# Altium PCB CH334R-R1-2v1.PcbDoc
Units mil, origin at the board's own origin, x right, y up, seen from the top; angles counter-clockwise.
Board outline 3110.24 x 866.14 mil, 2 copper layers (Top Layer, Bottom Layer); 16 components, 18 nets, 84 pads, 280 vias.
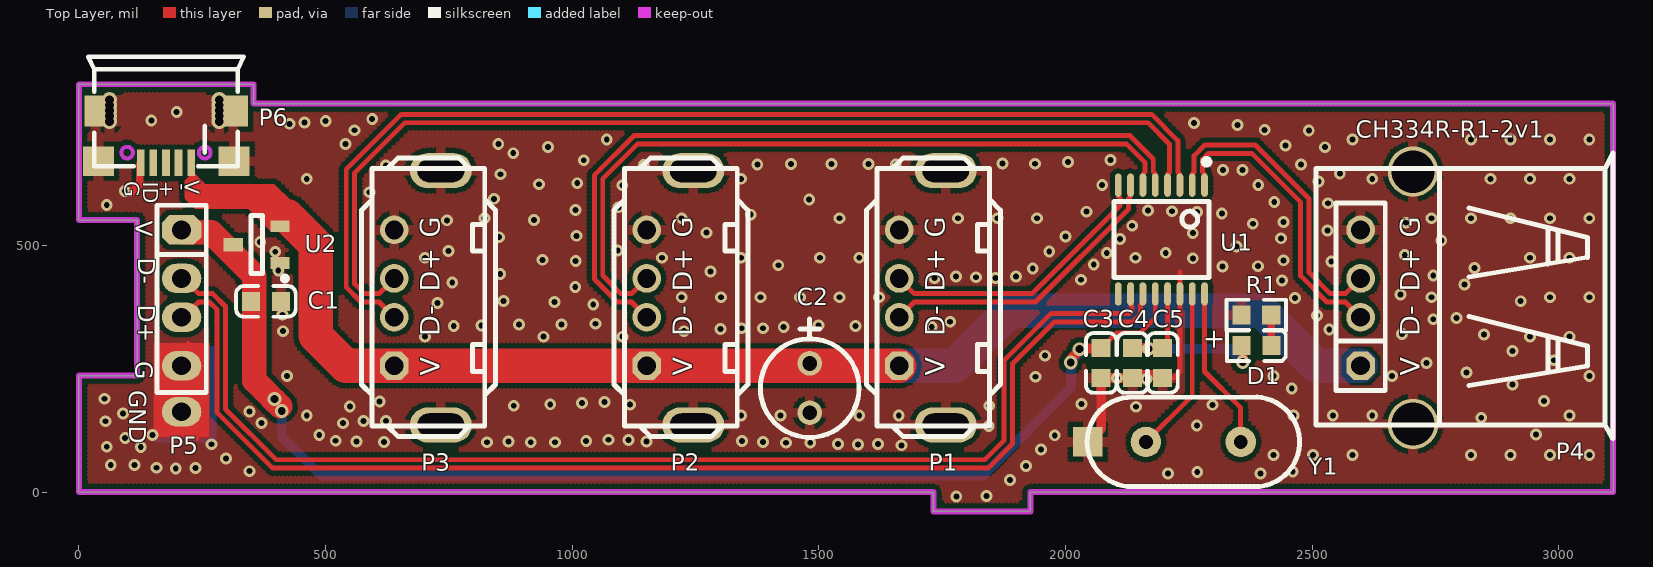
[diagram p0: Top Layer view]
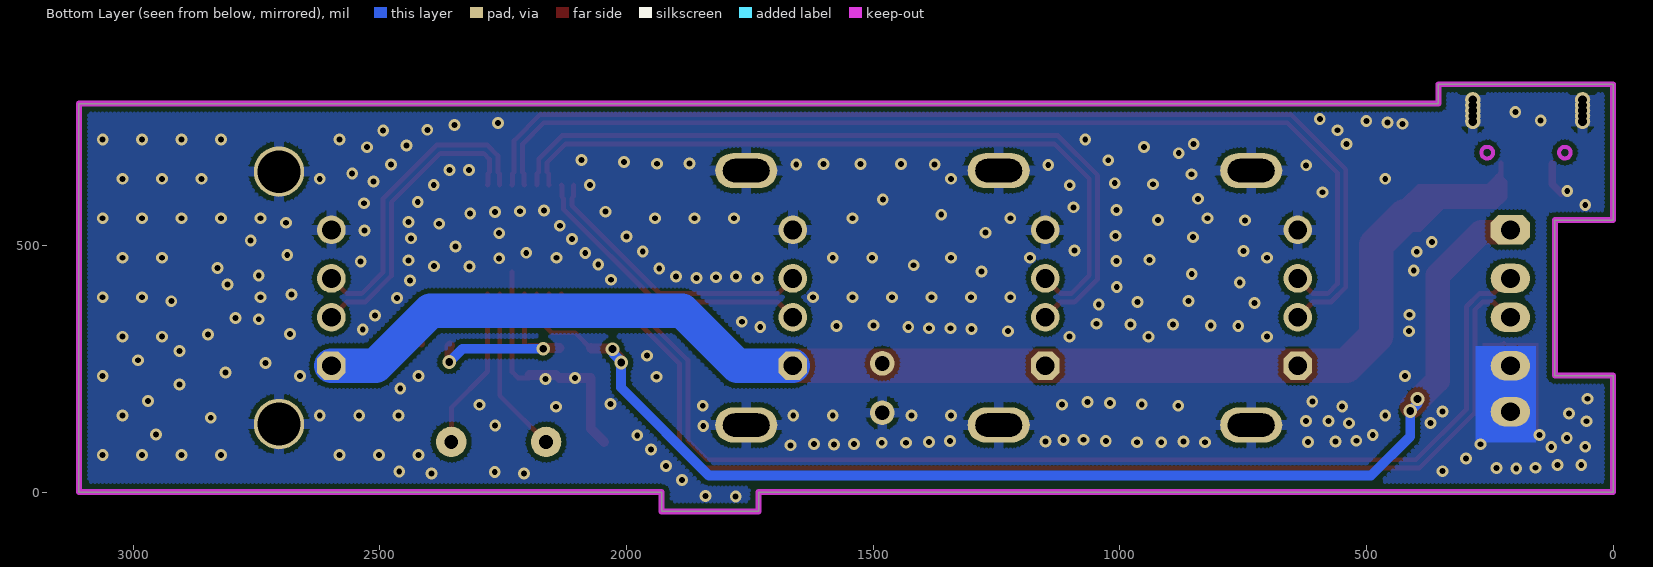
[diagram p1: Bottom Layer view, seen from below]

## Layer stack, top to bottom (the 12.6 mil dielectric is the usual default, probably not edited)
Top Solder: solder mask 0.4, Solder Resist, Dk 3.5
Top Layer: signal copper 1.4
Dielectric 1: dielectric 12.6, FR-4, Dk 4.8
Bottom Layer: signal copper 1.4
Bottom Solder: solder mask 0.4, Solder Resist, Dk 3.5

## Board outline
0,0 0,236.22 118.11,236.22 118.11,551.18 0,551.18 0,826.77 354.33,826.77 354.33,787.4 3110.24,787.4 3110.24,0 1929.13,0 1929.13,-39.37 1732.28,-39.37 1732.28,0

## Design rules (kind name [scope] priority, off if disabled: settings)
Clearance Clearance_1 [InPolygon] p1: gap=10 ignorepadtopadclearanceinfootprint=FALSE
Clearance [All] p2: gap=6 ignorepadtopadclearanceinfootprint=FALSE except(8: Arc-Via Track-Via SMDPad-Via THPad-Via Via-Via Via-Fill Via-Poly Via-Region Via-Hole)
ComponentClearance [All] p1 off: gap=10 collisioncheckmode=3 verticalgap=10 showdistances=FALSE
DiffPairsRouting [All] p1: maxlimit=10 minlimit=7 mostfreqgap=8 toplayer_minwidth=6 toplayer_maxwidth=15 toplayer_prefwidth=8 bottomlayer_minwidth=6 bottomlayer_maxwidth=15 bottomlayer_prefwidth=8 maxuncoupledlength=500
MinimumSolderMaskSliver [All] p1 off: minsoldermaskwidth=10
PolygonConnect PolygonConnect_1 [IsVia] p1: connectstyle=Direct reliefconductorwidth=10 reliefentries=4 polygonreliefangle="90 Angle" airgapwidth=10
PolygonConnect [All] p2: connectstyle=Relief reliefconductorwidth=20 reliefentries=4 polygonreliefangle="90 Angle" airgapwidth=10
RoutingVias [All] p1: holewidth=16 width=28 viastyle="Through Hole" minholewidth=12 minwidth=24 maxholewidth=28 maxwidth=50
SilkToSilkClearance [All] p1 off: silktosilkclearance=10
SilkToSolderMaskClearance [IsPad] p1 off: minsilkscreentomaskgap=10 clearancetoexposedcopper=TRUE
SolderMaskExpansion [All] p1: expansion=4 istentingtop=FALSE
Width [All] p1: maxlimit=100 minlimit=6 preferedwidth=10
25 further rules are at their usual default settings.

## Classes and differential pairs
component class CH334R-R1-2v1: C1 C2 D1 P1 P2 P3 P4 P5 P6 R1 U1 U2 Y1
differential pair UD: +UD_p -UD_n
differential pair UD4: +UD4_p -UD4_n
differential pair UD3: +UD3_p -UD3_n
differential pair UD2: +UD2_p -UD2_n
differential pair UD1: +UD1_p -UD1_n

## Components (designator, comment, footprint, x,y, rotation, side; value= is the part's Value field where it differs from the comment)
C1 "10uF" 0603_C 348.8,386.46 r0 top
C2 "220uF" CD0.1 1481.53,260.82 r270 top
C3 "1uF" 0603_C 2072.52,291.96 r270 top
C4 "0.1uF" 0603_C 2136.15,291.96 r270 top
C5 "10uF" 0603_C 2196.61,291.96 r270 top
D1 "LED" 0603+ 2357.27,297.04 r0 top
P1 "USB" USB2.0-A-F-TH_4P-V_13.7mm 1662.83,255.91 r180 top
P2 "USB" USB2.0-A-F-TH_4P-V_13.7mm 1151.02,255.91 r180 top
P3 "USB" USB2.0-A-F-TH_4P-V_13.7mm 639.21,255.91 r180 top
P4 "USB" USBAF#1 2598.25,255.91 r90 top
P5 "USB" USBAF#2 208.21,531.5 r270 top
P6 "PowerSupply" USBMICROB-02-GXPX-A1T2 227.66,667.45 r180 top
R1 "1K" 0603_R 2386.89,358.69 r0 top
U1 "CH334R" QSOP16 2282,622.22 r180 top
U2 "CH213K" SOT-23-3 407.7,464.3 r90 top
Y1 "12M" XT_AT49 2355.27,101.61 r90 top

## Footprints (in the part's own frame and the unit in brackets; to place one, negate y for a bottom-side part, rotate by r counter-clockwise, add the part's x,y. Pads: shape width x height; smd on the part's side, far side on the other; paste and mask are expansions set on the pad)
0603+ [mm]
  rect 0.93x0.98 smd: 1(0,0) 2(1.54,0)
  silkscreen extent -0.76,-0.79 2.27,0.79
0603_C [mm]
  rect 0.93x0.98 smd: 1(0,0) 2(1.54,0)
  silkscreen extent -0.76,-0.79 2.31,0.79
0603_R [mm]
  rect 0.93x0.98 smd: 1(-0.77,0) 2(0.77,0)
  silkscreen extent -1.53,-0.79 1.54,0.79
CD0.1 [mil]
  round 50 hole 30: 1(0,0) 2(100,0)
  silkscreen extent -90,-100 150,100
QSOP16 [mm]
  oval 0.35x1.2 smd mask+0.051: 1(0,0) 2(0.635,0) 3(1.27,0) 4(1.905,0) 5(2.54,0) 6(3.175,0) 7(3.81,0) 8(4.445,0) 9(4.445,5.6) 10(3.81,5.6) 11(3.175,5.6) 12(2.54,5.6) 13(1.905,5.6) 14(1.27,5.6) 15(0.635,5.6) 16(0,5.6)
  silkscreen extent -0.25,-1.35 4.67,4.75
SOT-23-3 [mm] "SOT-23-3"
  rect 0.6x1 smd: 1(0,0) 2(1.9,0)
  rect 0.7x1 smd: 3(0.95,2.4)
  silkscreen extent -0.93,-0.38 2.45,1.49
USB2.0-A-F-TH_4P-V_13.7mm [mm]
  oval 3.2x1.8 hole 1.2 slot 2.4 at 0 deg: 0(-2.4,3.05) 0(-2.4,-10.05)
  oct 1.473x1.473 hole 0.965: 1(0,0)
  round 1.473 hole 0.965: 2(0,-2.5) 3(0,-4.5) 4(0,-7)
  silkscreen extent -5.21,-10.71 1.69,3.65
USBAF#1 [mm]
  round 2.6 hole 2.2: 0(-3,-2.7) 0(10,-2.7)
  oct 1.473x1.473 hole 0.965: 1(0,0)
  round 1.473 hole 0.965: 2(2.5,0) 3(4.5,0) 4(7,0)
  silkscreen extent -3.75,-12.99 10.95,2.29
USBAF#2 [mm]
  oct 1.524x2.032 hole 0.965: 1(0,0)
  oval 1.524x2.032 hole 0.965: 2(2.5,0) 3(4.5,0) 4(7,0)
  silkscreen extent -1.27,-1.27 8.38,1.27
USBMICROB-02-GXPX-A1T2 [mm]
  rect 1.6x1.5 smd: 0(-2.203,-0.083) 0(4.769,-0.083)
  rect 1.5x1.6 smd: 0(-2.167,-2.675)
  round 0.8 hole 0.45: 0(-1.442,-2.134) 0(-1.442,-3.243) 0(-1.442,-2.966) 0(-1.442,-2.689) 0(-1.442,-2.411) 0(4.208,-2.689) 0(4.208,-2.411) 0(4.208,-2.134) 0(4.208,-3.243) 0(4.208,-2.966)
  rect 1.1x1.6 smd: 0(4.933,-2.675)
  rect 0.4x1.35 smd mask+0.051: 1(0,0) 2(0.65,0) 3(1.3,0) 4(1.95,0) 5(2.6,0)
  Keep-Out Layer circle w0.203: c3.3,-0.525 r0.3
  Keep-Out Layer circle w0.203: c-0.7,-0.525 r0.3
  silkscreen extent -2.7,-5.46 5.3,0.17
XT_AT49 [mil]
  rect 60x60 smd: 0(0,310)
  round 62 hole 28: 1(0,0) 2(0,192.13)
  silkscreen extent -91,-119 91,311

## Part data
C1 C2 C3 C4 C5: library part CAP, "Capacitor"
D1: "Typical INFRARED GaAs LED"
P1 P2 P3 P4 P5: "USB Port"
P6: library part MicroUSB, "MicroUSB Port"
R1: library part RES
U1: "4 ports High-Speed USB MTT Hub"
U2: "Ideal Diode 5V*1A"
Y1: library part XTAL, "Crystal Oscillator"

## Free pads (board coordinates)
  oval 80x60 hole 38: ""(208.21,162.81)

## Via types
v1: diameter 24, hole 12, Top Layer to Bottom Layer, tented both sides, 274 vias
v2: diameter 28, hole 16, Top Layer to Bottom Layer, tented both sides, 6 vias

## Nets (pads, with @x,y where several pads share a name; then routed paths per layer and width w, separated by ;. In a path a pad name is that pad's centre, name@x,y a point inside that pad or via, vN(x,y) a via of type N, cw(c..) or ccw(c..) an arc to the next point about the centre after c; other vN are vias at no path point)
3V3: C4.1 C5.1 D1.1 U1.13 | length 408
  Top Layer w10: C4.1@2137.15,291.96 C4.1@2143,297.81 ; C5.1@2207,297.81 U1.13
  Top Layer w20: C4.1 2137.15,291.96 C5.1 ; D1.1 2359.33,294.98 v2(2359.33,263.98)
  Bottom Layer w20: v2(2168.94,290.58) 2332.73,290.58 v2(2359.33,263.98)
5V: C1.1 C3.1 P5.1 U1.12 U2.3 | length 2623.4
  Top Layer w10: C3.1 2073.5,291.96 2086.81,305.27 2086.81,305.86 2103.95,323 2151.32,323 2182,353.67 U1.12
  Top Layer w20: v2(411.36,164.03) 416.39,164.03 v2@422.95,170.59 ; v2(2010.72,262.87) 2012.25,264.4 2012.25,271.31 2028.46,287.52 v2(2028.46,289.69) 2029.59,290.82 2071.38,290.82 C3.1
  Top Layer w50: P5.1 212.86,526.85 267.78,526.85 355.63,439.01 355.63,226.31 380.94,201 396.47,185.47 v2@407.93,174.01
  Bottom Layer w20: v2(396.4,188.39) 396.4,178.99 v2(411.36,164.03) 411.36,112.83 490.78,33.41 1833.3,33.41 2011.55,211.65 v2@2011.55,262.87 ; v2(2010.72,262.87) 2010.72,264.85 2026.92,281.05 2026.92,288.15 v2(2028.46,289.69)
GND: C1.2 C2.2 C3.2 C4.2 C5.2 P1.0 P1.4 P2.0 P2.4 P3.0 P3.4 P4.0 P4.4 P5.4 P6.0 P6.5 pad. R1.1 U1.14 U2.1 Y1.0 | length 1416.3
  Top Layer w8: 220.81,208.41 220.81,302.53 ; 222,112.53 222,206.65 ; 225,112.53 225,206.65 ; 227.09,204.87 227.09,299 ; 230,111.08 230,205.21 ; 233,204.17 233,298.3 ; 234,111.08 234,205.21 ; 240,107.99 240,202.11 ; 240,201.08 240,295.21
  Top Layer w10: C5.2 2219.76,231.33 2232,243.57 U1.14 2232,445.69
  Top Layer w15: 104.84,605.5 123.71,624.36 P6.5@123.71,665.85
  Top Layer w20: Y1.0 2072.52,128.86 C3.2 C4.2 ; C4.2@2143.01,237.19 C5.2@2196.84,237.19
  other v1: 1778.73,-8.71 1840.22,-8.03 1887.35,24.77 2207.89,37.74 2395.65,37.74 2267.23,40.66 345.77,42.29 2460.84,41.63 196.36,47.86 157.58,49.29 236.59,48.81 1920.15,52.78 64.67,55.04 112.56,54.56 298,68.06 2422,75 2502,75 2582,75 2822,75 2902,75 2982,75 3062,75 1950.66,86.04 125.49,91.43 56.53,91.91 1667.91,94.8 1579.29,96.19 269.09,96.97 1538.7,97.13 1619.89,97.13 1433.25,99.93 1482.71,99.93 618.87,101.5 827.57,100.97 916.07,100.97 965.42,100.97 1387.05,101.79 563.05,102.8 870.97,102.68 1150.93,102.68 1344.12,103.19 520.64,104.1 1028.39,103.53 1114.34,105.23 1073.49,106.08 93.89,109.63 149.43,115.38 487.31,115.35 1978.31,115.02 2953.66,116.98 1844.44,134.08 2266.26,135.03 370.18,139.83 535.35,139.58 54.14,143.63 576.89,143.91 622.77,143.91 2842.89,150.73 462,155 1342,155 1422,155 1582,155 1662,155 2462,155 2542,155 2622,155 3022,155 89.58,159.43 345.61,163.53 549.2,173.34 2142.7,172.97 881.63,174.96 1845.46,174.9 1117.55,177.16 2298.37,176.86 955.63,177.89 2032.77,178.81 1020.11,180.82 1065.53,182.28 609.78,183.72 2970.04,184.47 51.74,189.12 2458.75,210.12 2906.47,218.22 2164.11,229.4 2104.33,231.33 1939.6,233.84 422,235 2422,235 2662,235 3062,235 2813.04,242.58 2732.05,261.79 2990.27,267.24 1958.24,276.44 2906.47,285.71 702,315 942,315 1102,315 2942,315 3022,315 2848.67,319.45 2681.97,320.55 413.66,326.13 1226.76,326.1 2534.74,329.82 1300.83,330.59 1343.48,332.09 1386.87,332.09 1428.77,334.33 1729.02,334.29 760.01,336.88 1574.67,336.58 815.69,337.61 1499.1,338.07 891.89,339.81 978.34,339.81 1047.21,341.27 1766.3,345.33 2745.54,350.41 2792.74,353.2 2509.66,357.69 412.8,359.39 1042.82,380.11 727.04,383.04 964.42,385.23 861.12,387.43 2922.84,386.94 2465.07,393.22 1222,395 1302,395 1382,395 1462,395 1542,395 1622,395 2742,395 2982,395 3062,395 2679.08,400.49 1006.25,415.39 2809.11,420.69 756.97,424.97 2439.29,428.75 2031.58,430.46 1734.72,434.11 1858.17,433.67 1818.93,435.43 1777.93,437.19 1899.61,437.19 2745.54,439.02 854.15,442.07 1280.14,447.3 404.16,449.22 1933.64,453.26 2829.34,454.43 2318.61,457.18 2390.27,457.86 1417.86,459.82 2057.34,461.24 2538.92,467.07 1007.16,468.13 2441.92,469.79 939.67,470.84 2258.17,473.88 702,475 1182,475 1342,475 1502,475 1582,475 2142,475 2942,475 3022,475 2687.75,480.44 2083.77,484.66 2203.29,485.01 398.12,487.22 1967.08,487.34 749.2,488.72 1092.03,489.51 2346.44,497.74 367.59,507.14 2761.91,510.3 2110.87,513.1 2437.2,514.45 851.82,516.71 1999.87,518.2 1009,519.49 2258.17,524.78 1272.17,525.84 2531.26,530.47 2135.3,539.87 2379.84,543.86 2690.64,545.94 2441.92,547.33 746.09,550.91 922.56,551.69 822,555 1222,555 1542,555 1782,555 1862,555 1942,555 2742,555 2822,555 2902,555 2982,555 3062,555 1362.09,562.26 2316.97,564.62 2042.94,568.35 2266.79,567.64 2216.26,569.31 1006.71,571.47 2167.42,570.65 1093.71,577.24 56.52,582.14 2531.95,585.51 2423.27,588.3 1480.46,592.99 841.71,594.45 589.23,607.79 93.02,610.17 1101.53,621.94 2074.45,622.36 2390.91,622.82 932.67,623.99 1010.25,626.12 2513.03,629.78 462,635 1342,635 2622,635 2862,635 2942,635 3022,635 854.93,644.21 2556.15,645.98 2319.69,652.63 2358.96,652.63 622.24,662.42 1145.12,662.73 1375.3,663.89 1655.97,663.89 2477.67,664.37 1443.81,664.72 1525.54,664.72 1600.66,664.72 1872.62,666.27 1938,665.57 2005.49,669.08 1023.41,672.66 2091.25,673.3 880.58,686.96 951.33,699.4 2526.2,699.11 2446.15,702.81 540.34,705.78 850.26,705.62 1070.19,714.85 2582,715 2822,715 2902,715 2982,715 3062,715 559.03,733.42 2493.35,732.93 2403.88,734.32 2348.53,744.32 426.68,746.52 2260.9,748.16 457.39,749.48 500.31,752.44 146.87,753.14 594.64,756.14 198.29,770.28
NetD1_2: D1.2 R1.2 | length 58.8
  Top Layer w15: D1.2@2415.65,300.86 2417.55,302.77 2417.55,358.35 R1.2
NetU1_15: U1.15 Y1.2 | length 339
  Top Layer w10: Y1.2 2257,195.47 U1.15
NetU1_16: U1.16 Y1.1 | length 330.5
  Top Layer w10: U1.16 2282,244.37 2355.27,171.1 Y1.1
RST: U1.9
UD1_n: P1.2 U1.7 | length 606.1
  Top Layer w10: P1.2 1693.7,385.2 1939.34,385.2 2128,573.86 2128,595.53 2131.28,598.81 2131.28,621.5 U1.7
UD1_p: P1.3 U1.8 | length 577.9
  Top Layer w10: P1.3 1693.7,402.2 1932.3,402.2 2111,580.9 2111,595.53 2107.72,598.81 2107.72,621.5 U1.8
UD2_n: P2.2 U1.5 | length 1589.1
  Top Layer w10: P2.2 1120.15,385.2 1091.69,385.2 1045,431.89 1045,642.04 1125.69,722.73 2130.56,722.73 2178,675.29 2178,648.91 2181.28,645.63 2181.28,622.94 U1.5
UD2_p: P2.3 U1.6 | length 1504.6
  Top Layer w10: P2.3 1120.15,402.2 1098.73,402.2 1062,438.93 1062,635 1132.73,705.73 2123.52,705.73 2161,668.25 2161,648.91 2157.72,645.63 2157.72,622.94 U1.6
UD3_n: P3.2 U1.3 | length 2207.5
  Top Layer w10: P3.2 608.34,385.2 571.8,385.2 542,415 542,654.04 653.57,765.61 2174.79,765.61 2228,712.4 2228,648.91 2231.28,645.63 2231.28,622.94 U1.3
UD3_p: P3.3 U1.4 | length 2123
  Top Layer w10: P3.3 608.34,402.2 578.84,402.2 559,422.04 559,647 660.61,748.61 2167.75,748.61 2211,705.36 2211,648.91 2207.72,645.63 2207.72,622.94 U1.4
UD4_n: P4.2 U1.1 | length 604.4
  Top Layer w10: U1.1 2281.28,622.94 2281.28,645.63 2278,648.91 2278,674.83 2289.75,686.58 2377.53,686.58 2476.69,587.42 2476.69,438.27 2529.76,385.2 2567.38,385.2 P4.2
UD4_p: P4.3 U1.2 | length 632.5
  Top Layer w10: U1.2 2257.72,622.94 2257.72,645.63 2261,648.91 2261,681.88 2282.71,703.58 2384.57,703.58 2493.69,594.46 2493.69,445.31 2536.8,402.2 2567.38,402.2 P4.3
UD_n: P5.2 U1.10 | length 2456.9
  Top Layer w10: P5.2 211.83,433.07 242.7,402.2 271.31,402.2 297.25,376.26 297.25,168.13 399.94,65.44 1836.48,65.44 1875.78,104.74 1875.78,267.41 1970.19,361.82 2129.24,361.82 2135.11,367.7 2135.11,375.98 2132.72,378.37 2132.72,401.02 U1.10
UD_p: P5.3 U1.11 | length 2485.8
  Top Layer w10: P5.3 211.83,354.33 242.7,385.2 264.27,385.2 280.25,369.22 280.25,161.09 392.9,48.44 1843.52,48.44 1892.78,97.7 1892.78,260.37 1977.23,344.82 2136.28,344.82 2152.11,360.66 2152.11,379.1 2157,383.99 U1.11
VBUS: C2.1 P1.1 P2.1 P3.1 P4.1 P6.1 U2.2 | length 3758.1
  Top Layer w10: 247.13,591.38 252.13,591.38 ; 252.85,603.63 251.45,605.02 ; 252.85,608.63 252.85,605.02 ; 254.37,584.14 259.37,584.14 ; U2.2@389.09,543.8 348.75,584.14 259.37,584.14 ; U2.2@399.83,539.1 U2.2 ; U2.2@401.09,540.36 350.07,591.38 266.49,591.38 ; U2.2@422.51,532.57 391.4,532.57 344.33,579.63 263.88,579.63 ; 422.68,559.1 376.75,605.02 269.41,605.02 ; 219.15,602.21 241.73,579.63 ; 219.15,602.21 219.15,629.22 226.76,636.83 226.76,666.54 P6.1 P6.1@227.66,646.78 ; 219.15,602.21 219.15,597.21 236.73,579.63 241.73,579.63 ; 227.66,615.85 227.66,619.83 ; 227.66,615.85 227.66,604.47 252.5,579.63 ; 227.66,615.85 238.49,605.02 ; 227.66,619.83 227.66,628.81 ; 227.66,619.83 242.47,605.02 ; 227.66,628.81 251.45,605.02 ; 227.66,628.81 P6.1@227.66,646.78 ; P6.1@227.66,646.78 234.14,640.3 ; 234.14,640.3 269.41,605.02 ; 234.14,640.3 234.14,633.09 262.21,605.02 ; 238.49,605.02 242.47,605.02 ; 238.49,605.02 252.13,591.38 ; 241.73,579.63 252.5,579.63 ; 242.47,605.02 251.45,605.02 ; 242.47,605.02 247.47,600.02 257.85,600.02 ; 251.45,605.02 252.85,605.02 ; 252.13,591.38 266.49,591.38 ; 252.13,591.38 259.37,584.14 ; 252.5,579.63 263.88,579.63 ; 252.85,605.02 262.21,605.02 ; 252.85,605.02 257.85,600.02 ; 257.85,600.02 266.49,591.38 ; 257.85,600.02 267.21,600.02 ; 259.37,584.14 263.88,579.63 ; 262.21,605.02 269.41,605.02 ; 262.21,605.02 267.21,600.02 ; 267.21,600.02 274.41,600.02 269.41,605.02
  Top Layer w70: 422.68,559.1 480.22,501.56 480.22,316.93 541.24,255.91 P3.1 P2.1 P1.1
  Bottom Layer w70: P1.1 1775.33,255.91 1886.87,367.44 2397.41,367.44 2508.95,255.91 P4.1
pads on no net: P6.2 P6.3 P6.4

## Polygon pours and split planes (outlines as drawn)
GND on Bottom Layer "GND" (hatched 90Degree grid 8 track 8, remove dead copper, pour order 1): 0,826.77 0,551.18 118.11,551.18 118.11,236.22 0,236.22 0,0 1732.28,0 1732.28,-39.37 1929.13,-39.37 1929.13,0 3110.24,0 3110.24,787.4 354.33,787.4 354.33,826.77
GND on Top Layer "GND" (hatched 90Degree grid 8 track 8, remove dead copper, pour order 0): 0,826.77 0,551.18 118.11,551.18 118.11,236.22 0,236.22 0,0 1732.28,0 1732.28,-39.37 1929.13,-39.37 1929.13,0 3110.24,0 3110.24,787.4 354.33,787.4 354.33,826.77

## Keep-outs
Keep-Out Layer:
  the board outline again, w12

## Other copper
Top Layer:
  rectangle net GND: 151.31,111.08 265.24,302.38
  region net VBUS: 235.03,574.76 344.34,574.76 391.5,527.6 431.6,527.6 431.6,589.35 396.55,624.39 232.88,624.39
Bottom Layer:
  rectangle net GND: 156.56,100.86 278.7,295.9

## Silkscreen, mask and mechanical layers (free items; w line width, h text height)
Top Overlay:
  lines w10: 255.22,688.11 255.22,741.9
  text "CH334R-R1-2v1" at 2588.77,717.88 h35
  text "GND" at 102.23,206.83 h35 r270
Mechanical 1:
  lines w10: 0,0 0,236.22 118.11,236.22 118.11,551.18 0,551.18 0,787.4 0,826.77 354.33,826.77 354.33,787.4 3110.24,787.4 3110.24,0 1929.13,0 1929.13,-39.37 1732.28,-39.37 1732.28,0 0,0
